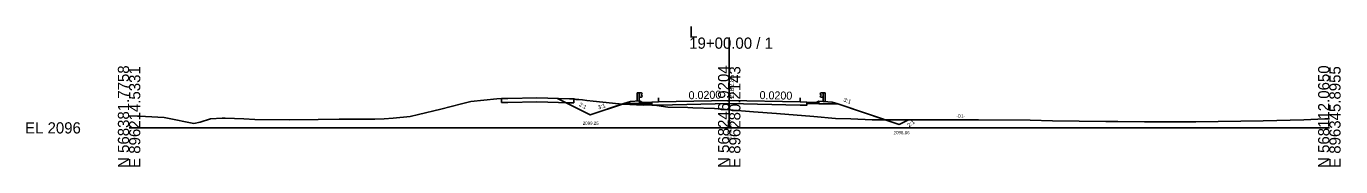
# Model space of a CAD drawing. Extents: x -26 to 1603, y -10 to 13527.
# Drawn here: x -25.7 to 302.8, y 6490.3 to 6525.4 of the extents above; entities that cross this region are included whole.
import ezdxf

# ---------------------------------------------------------------- set-up
doc = ezdxf.new("R2010")
doc.units = 0
for name, color, linetype in [('Default', 7, 'Continuous'), ('Exist XS Center Line Elevation Label', 7, 'Continuous'), ('Exist XS Ground Line', 7, 'Continuous'), ('Old_Level_3', 7, 'Continuous'), ('Old_Level_61', 7, 'Continuous'), ('Old_Level_63', 7, 'Continuous'), ('Prop XS Ditch Slope Text', 7, 'Continuous'), ('Prop XS Ditch Standard Text', 7, 'Continuous'), ('Prop XS Dump Level', 7, 'Continuous'), ('Prop XS Earthwork Shape', 7, 'Continuous'), ('Prop XS EOT Tick Mark', 7, 'Continuous'), ('Prop XS Finish Grade', 7, 'Continuous'), ('Prop XS Finish Grade Earthwork', 7, 'Continuous'), ('Prop XS Finish Grade Paved Shoulder', 7, 'Continuous'), ('Prop XS Finish Grade Pavement', 7, 'Continuous'), ('Prop XS Side Slope Text', 7, 'Continuous'), ('Prop XS Subgrade Earthwork', 7, 'Continuous'), ('Prop XSC Text', 7, 'Continuous'), ('Typical Curb CELL', 7, 'Continuous')]:
    doc.layers.add(name, color=color, linetype=linetype)

msp = doc.modelspace()

# ---------------------------------------------------------------- linework, layer by layer
at = {"layer": 'Exist XS Ground Line'}
for p, q in [((77.94, 6504.71), (83.07, 6506.02)), ((83.07, 6506.02), (85.39, 6506.6)), ((85.39, 6506.6), (91.88, 6507.23)), ((91.88, 6507.23), (93.11, 6507.35)), ((93.11, 6507.35), (94.63, 6507.38)), ((94.63, 6507.38), (101.93, 6507.52)), ((101.93, 6507.52), (110.12, 6507.27)), ((110.12, 6507.27), (111.14, 6507.25)), ((111.14, 6507.25), (111.76, 6507.13)), ((111.76, 6507.13), (112.41, 6507.08)), ((112.41, 6507.08), (113.34, 6506.98)), ((113.34, 6506.98), (114.41, 6506.86)), ((114.41, 6506.86), (116.03, 6506.64)), ((116.03, 6506.64), (120.86, 6506.14)), ((120.86, 6506.14), (121.6, 6506.06)), ((121.6, 6506.06), (123.39, 6505.92)), ((123.39, 6505.92), (128.54, 6505.64)), ((128.54, 6505.64), (130.49, 6505.75)), ((130.49, 6505.75), (131.9, 6505.56)), ((131.9, 6505.56), (134.65, 6505.2)), ((134.65, 6505.2), (139.69, 6505.08)), ((139.69, 6505.08), (140.93, 6505.02)), ((140.93, 6505.02), (146.33, 6504.87)), ((0, 6503), (4.13, 6502.87)), ((4.13, 6502.87), (8.76, 6502.58)), ((8.76, 6502.58), (9.57, 6502.4)), ((9.57, 6502.4), (16.15, 6501.09)), ((17.79, 6501.42), (20.35, 6502.27)), ((20.35, 6502.27), (23.3, 6502.41)), ((23.3, 6502.41), (24.02, 6502.45)), ((24.02, 6502.45), (28.68, 6502.23)), ((28.68, 6502.23), (31.43, 6502.12)), ((31.43, 6502.12), (40.14, 6502.03)), ((40.14, 6502.03), (47.26, 6502.08)), ((47.26, 6502.08), (52.52, 6502.16)), ((52.52, 6502.16), (61.44, 6502.21)), ((61.44, 6502.21), (63.72, 6502.24)), ((63.72, 6502.24), (65.97, 6502.46)), ((65.97, 6502.46), (70.26, 6502.87)), ((70.26, 6502.87), (72.34, 6503.36)), ((72.34, 6503.36), (77.94, 6504.71)), ((146.33, 6504.87), (150, 6504.55)), ((150, 6504.55), (156.07, 6504.03)), ((156.07, 6504.03), (161.81, 6503.58)), ((161.81, 6503.58), (171.18, 6502.81)), ((171.18, 6502.81), (176.58, 6502.38)), ((176.58, 6502.38), (180.42, 6502.24)), ((180.42, 6502.24), (185.74, 6502.03)), ((185.74, 6502.03), (198.55, 6502.02)), ((198.55, 6502.02), (202.65, 6501.97)), ((202.65, 6501.97), (212.27, 6501.98)), ((212.27, 6501.98), (225.23, 6501.9)), ((225.23, 6501.9), (230.81, 6501.8)), ((230.81, 6501.8), (244.15, 6501.59)), ((266.61, 6501.54), (283.42, 6501.72)), ((283.42, 6501.72), (293.64, 6501.98)), ((293.64, 6501.98), (298.9, 6502.23)), ((298.9, 6502.23), (300, 6502.26)), ((16.15, 6501.09), (17.79, 6501.42)), ((244.15, 6501.59), (247.13, 6501.56)), ((247.13, 6501.56), (253.78, 6501.5)), ((253.78, 6501.5), (263.38, 6501.49)), ((263.38, 6501.49), (266.61, 6501.54))]:
    msp.add_line(p, q, dxfattribs=at)
at = {"layer": 'Old_Level_3'}
for p, q in [((126.98, 6506.69), (126.98, 6508.79)), ((126.98, 6508.79), (127.48, 6508.79)), ((127.48, 6508.79), (127.48, 6506.72)), ((127.48, 6508.79), (127.98, 6508.79)), ((127.98, 6508.79), (128.27, 6508.59)), ((128.27, 6508.47), (127.98, 6508.27)), ((127.98, 6508.27), (127.98, 6508.18)), ((128.27, 6508.59), (128.3, 6508.53)), ((128.3, 6508.53), (128.27, 6508.47)), ((172.73, 6508.57), (172.7, 6508.51)), ((172.7, 6508.51), (172.73, 6508.45)), ((173.02, 6508.77), (172.73, 6508.57)), ((172.73, 6508.45), (173.02, 6508.25)), ((173.52, 6508.77), (173.02, 6508.77)), ((173.02, 6508.25), (173.02, 6508.16)), ((174.02, 6508.77), (173.52, 6508.77)), ((173.52, 6508.77), (173.52, 6506.59)), ((174.02, 6506.56), (174.02, 6508.77)), ((127.98, 6507.66), (127.48, 6507.66)), ((127.98, 6508.18), (128.27, 6507.98)), ((128.27, 6507.86), (127.98, 6507.66)), ((128.27, 6507.98), (128.3, 6507.92)), ((128.3, 6507.92), (128.27, 6507.86)), ((172.73, 6507.96), (172.7, 6507.9)), ((172.7, 6507.9), (172.73, 6507.84)), ((173.02, 6508.16), (172.73, 6507.96)), ((172.73, 6507.84), (173.02, 6507.64)), ((173.02, 6507.64), (173.52, 6507.64))]:
    msp.add_line(p, q, dxfattribs=at)
at = {"layer": 'Old_Level_61'}
for p, q in [((93.11, 6507.35), (93.11, 6506.35)), ((93.11, 6506.35), (94.11, 6506.37)), ((94.11, 6506.37), (94.63, 6506.38)), ((94.63, 6506.38), (101.93, 6506.52)), ((101.93, 6506.52), (110.12, 6506.27)), ((110.12, 6506.27), (111.14, 6506.25)), ((111.14, 6506.25), (111.14, 6507.25))]:
    msp.add_line(p, q, dxfattribs=at)
at = {"layer": 'Old_Level_63'}
for p, q in [((150, 6500), (150, 6522.57)), ((0, 6500), (150, 6500)), ((150, 6500), (300, 6500))]:
    msp.add_line(p, q, dxfattribs=at)
at = {"layer": 'Prop XS Earthwork Shape'}
for points in [[(121.6, 6506.06), (123.31, 6505.93), (115.28, 6503.25), (107.05, 6507.37), (110.12, 6507.27), (111.14, 6507.25), (111.76, 6507.13), (112.41, 6507.08), (113.34, 6506.98), (114.41, 6506.86), (116.03, 6506.64), (120.86, 6506.14)], [(130.63, 6505.73), (130.63, 6506.05), (127.61, 6506.05), (123.67, 6506.05), (123.31, 6505.93), (123.39, 6505.92), (128.54, 6505.64), (130.49, 6505.75)], [(130.63, 6505.67), (130.63, 6505.73), (131.02, 6505.68)], [(172.39, 6505.98), (169.37, 6506.05), (169.37, 6505.67), (167.71, 6505.7), (150, 6506.06), (132.29, 6505.7), (131.02, 6505.68), (131.9, 6505.56), (134.65, 6505.2), (139.69, 6505.08), (140.93, 6505.02), (146.33, 6504.87), (150, 6504.55), (156.07, 6504.03), (161.81, 6503.58), (171.18, 6502.81), (176.58, 6502.38), (180.42, 6502.24), (185.74, 6502.03), (189, 6502.03), (177.15, 6505.98)], [(189, 6502.03), (194.84, 6502.02), (192.51, 6500.86)]]:
    msp.add_lwpolyline(points, close=True, dxfattribs=at)
at = {"layer": 'Prop XS EOT Tick Mark'}
for p, q in [((132.29, 6506.5), (132.29, 6507.5)), ((132.29, 6506.5), (132.29, 6507.5)), ((167.71, 6506.5), (167.71, 6507.5))]:
    msp.add_line(p, q, dxfattribs=at)
at = {"layer": 'Prop XS Finish Grade'}
for p, q in [((125.29, 6506.58), (123.67, 6506.05)), ((127.61, 6506.72), (125.29, 6506.58)), ((128.29, 6506.38), (127.61, 6506.72)), ((172.41, 6506.66), (175.71, 6506.46)), ((175.71, 6506.46), (177.15, 6505.98))]:
    msp.add_line(p, q, dxfattribs=at)
at = {"layer": 'Prop XS Finish Grade Earthwork'}
for p, q in [((115.28, 6503.25), (107.05, 6507.37)), ((123.67, 6506.05), (115.28, 6503.25)), ((177.15, 6505.98), (192.51, 6500.86)), ((192.51, 6500.86), (194.84, 6502.02))]:
    msp.add_line(p, q, dxfattribs=at)
at = {"layer": 'Prop XS Finish Grade Paved Shoulder'}
for p, q in [((132.29, 6506.5), (130.62, 6506.46)), ((167.71, 6506.5), (169.38, 6506.46))]:
    msp.add_line(p, q, dxfattribs=at)
at = {"layer": 'Prop XS Finish Grade Pavement'}
for p, q in [((132.29, 6506.5), (150, 6506.85)), ((150, 6506.85), (167.71, 6506.5))]:
    msp.add_line(p, q, dxfattribs=at)
at = {"layer": 'Prop XS Subgrade Earthwork'}
for p, q in [((127.61, 6506.05), (123.67, 6506.05)), ((130.63, 6506.05), (127.61, 6506.05)), ((130.63, 6505.67), (130.63, 6506.05)), ((132.29, 6505.7), (130.63, 6505.67)), ((150, 6506.06), (132.29, 6505.7)), ((167.71, 6505.7), (150, 6506.06)), ((167.71, 6505.7), (169.37, 6505.67)), ((169.37, 6505.67), (169.37, 6506.05)), ((172.39, 6505.98), (169.37, 6506.05)), ((172.39, 6505.98), (177.15, 6505.98))]:
    msp.add_line(p, q, dxfattribs=at)
at = {"layer": 'Typical Curb CELL'}
for p, q in [((127.61, 6506.05), (127.61, 6506.72)), ((128.29, 6506.38), (127.61, 6506.72)), ((127.61, 6506.05), (130.63, 6506.05)), ((127.64, 6506.34), (127.8, 6506.39)), ((127.78, 6506.3), (127.64, 6506.34)), ((127.8, 6506.39), (127.78, 6506.3)), ((128.31, 6506.26), (128.21, 6506.19)), ((128.21, 6506.19), (128.37, 6506.15)), ((130.62, 6506.46), (128.29, 6506.38)), ((128.37, 6506.15), (128.31, 6506.26)), ((129.05, 6506.32), (129.02, 6506.2)), ((129.02, 6506.2), (129.14, 6506.2)), ((129.14, 6506.2), (129.05, 6506.32)), ((129.56, 6506.26), (129.46, 6506.19)), ((129.46, 6506.19), (129.62, 6506.15)), ((129.62, 6506.15), (129.56, 6506.26)), ((130.3, 6506.32), (130.27, 6506.2)), ((130.27, 6506.2), (130.39, 6506.2)), ((130.39, 6506.2), (130.3, 6506.32)), ((130.63, 6506.46), (130.63, 6506.46)), ((130.63, 6506.05), (130.63, 6506.45)), ((169.37, 6506.05), (169.38, 6506.45)), ((172.39, 6505.98), (169.37, 6506.05)), ((169.38, 6506.46), (169.38, 6506.46)), ((169.4, 6506.46), (171.71, 6506.33)), ((169.62, 6506.19), (169.7, 6506.31)), ((169.74, 6506.2), (169.62, 6506.19)), ((169.7, 6506.31), (169.74, 6506.2)), ((170.38, 6506.12), (170.44, 6506.24)), ((170.55, 6506.16), (170.38, 6506.12)), ((170.44, 6506.24), (170.55, 6506.16)), ((170.87, 6506.16), (170.95, 6506.28)), ((170.99, 6506.17), (170.87, 6506.16)), ((170.95, 6506.28), (170.99, 6506.17)), ((171.63, 6506.1), (171.69, 6506.21)), ((171.79, 6506.13), (171.63, 6506.1)), ((171.69, 6506.21), (171.79, 6506.13)), ((171.71, 6506.33), (172.41, 6506.66)), ((172.21, 6506.33), (172.23, 6506.24)), ((172.36, 6506.28), (172.21, 6506.33)), ((172.23, 6506.24), (172.36, 6506.28)), ((172.39, 6505.98), (172.41, 6506.66))]:
    msp.add_line(p, q, dxfattribs=at)
for centre in [(127.67, 6506.43), (127.77, 6506.16), (127.89, 6506.21), (128.14, 6506.24), (128.16, 6506.19), (128.34, 6506.1), (128.37, 6506.2), (128.56, 6506.16), (128.61, 6506.28), (128.73, 6506.25), (128.77, 6506.12), (128.82, 6506.16), (129.02, 6506.16), (129.14, 6506.21), (129.23, 6506.2), (129.33, 6506.15), (129.38, 6506.3), (129.39, 6506.24), (129.41, 6506.19), (129.62, 6506.2), (129.81, 6506.16), (129.86, 6506.28), (129.91, 6506.25), (129.98, 6506.25), (130.02, 6506.12), (130.07, 6506.16), (130.13, 6506.34), (130.5, 6506.41), (130.54, 6506.28), (169.47, 6506.28), (169.51, 6506.41), (169.88, 6506.32), (169.93, 6506.14), (169.99, 6506.11), (170.02, 6506.24), (170.1, 6506.23), (170.15, 6506.26), (170.19, 6506.14), (170.39, 6506.18), (170.59, 6506.16), (170.61, 6506.21), (170.62, 6506.27), (170.68, 6506.12), (170.77, 6506.17), (170.87, 6506.17), (170.99, 6506.12), (171.18, 6506.12), (171.24, 6506.08), (171.27, 6506.21), (171.4, 6506.23), (171.44, 6506.12), (171.64, 6506.15), (171.66, 6506.05), (171.84, 6506.13), (171.86, 6506.18), (172.12, 6506.15), (172.24, 6506.09), (172.34, 6506.36)]:
    msp.add_circle(centre, 0.00802, dxfattribs=at)
for centre, start, end in [((130.62, 6506.45), 0, 92.048), ((169.39, 6506.45), 86.6704, 178.7184)]:
    msp.add_arc(centre, 0.0104, start, end, dxfattribs=at)

# ---------------------------------------------------------------- texts
at = {"layer": 'Default'}
for rotation, p in [(1.1458, (139.86, 6507.15)), (358.8542, (157.57, 6507.2))]:
    msp.add_text('0.0200', height=2, rotation=rotation, dxfattribs=at).set_placement(p)
at = {"layer": 'Exist XS Center Line Elevation Label'}
msp.add_text('2100.55', height=1, rotation=90, dxfattribs=at).set_placement((150.5, 6496.99))
at = {"layer": 'Old_Level_63'}
for s, p in [('L', (140, 6522.57)), ('19+00.00 / 1', (140, 6519.77)), ('EL 2096', (-26, 6498.6))]:
    msp.add_text(s, height=2.8, dxfattribs=at).set_placement(p)
for s, p in [('N 568381.7758', (0, 6490)), ('E 896214.5331', (2.8, 6490)), ('N 568246.9204', (150, 6490)), ('E 896280.2143', (152.8, 6490)), ('N 568112.0650', (300, 6490)), ('E 896345.8955', (302.8, 6490))]:
    msp.add_text(s, height=2.8, rotation=90, dxfattribs=at).set_placement(p)
at = {"layer": 'Prop XS Ditch Slope Text'}
msp.add_text('3:1', height=1, rotation=18.8342, dxfattribs=at).set_placement((117.36, 6504.58))
at = {"layer": 'Prop XS Ditch Standard Text'}
for s, p in [('-D1-', (206.79, 6502.57)), ('2099.25', (113.38, 6500.76)), ('2096.86', (191.08, 6498.42))]:
    msp.add_text(s, height=0.8, dxfattribs=at).set_placement(p)
at = {"layer": 'Prop XS Dump Level'}
msp.add_text('Case1', height=0.04, dxfattribs=at).set_placement((171.71, 6506.14))
at = {"layer": 'Prop XS Side Slope Text'}
for s, rotation, p in [('2:1', 333.4443, (112.35, 6505.51)), ('3:1', 338.821, (178.45, 6506.66)), ('2:1', 37.5433, (194.98, 6500.13))]:
    msp.add_text(s, height=1, rotation=rotation, dxfattribs=at).set_placement(p)
at = {"layer": 'Prop XSC Text'}
msp.add_text(' 2102.85', height=1.2, rotation=90, dxfattribs=at).set_placement((151.2, 6506.85))

doc.saveas('drawing.dxf')
